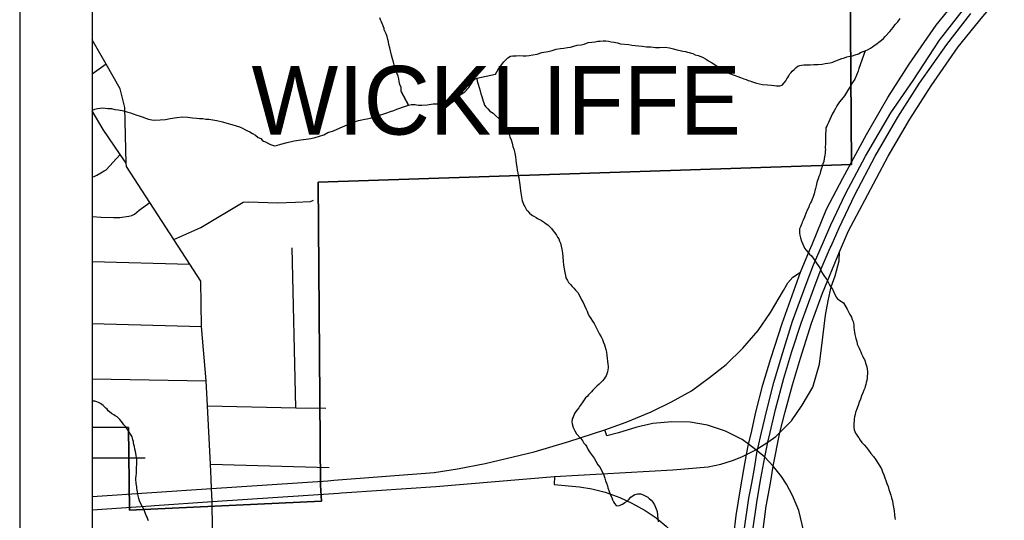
# Model space of a CAD drawing. Extents: x 0 to 44.3, y 0 to 22.
# Drawn here: x 2 to 3.359, y 14.762 to 15.453 of the extents above; entities that cross this region are included whole.
import ezdxf

# ---------------------------------------------------------------- set-up
doc = ezdxf.new("R2010")
doc.units = 0
for name, color, linetype in [('GM_X_City_Street', 7, 'Continuous'), ('GM_X_Corporation', 7, 'Continuous'), ('GM_X_Corporation_Text', 7, 'Continuous'), ('GM_X_County_Road', 7, 'Continuous'), ('GM_X_Interchange_Ramps', 7, 'Continuous'), ('GM_X_Interstate_Route', 7, 'Continuous'), ('GM_X_Interstate_Shield', 7, 'Continuous'), ('GM_X_Minor_River', 7, 'Continuous'), ('SH_Data', 7, 'Continuous')]:
    doc.layers.add(name, color=color, linetype=linetype)

msp = doc.modelspace()

# ---------------------------------------------------------------- linework, layer by layer
at = {"layer": 'GM_X_City_Street'}
for p, q in [((2.1193, 15.3916), (2.1, 15.3781)), ((2.3812, 14.9177), (2.3763, 15.1381)), ((2.1, 15.1194), (2.2347, 15.116)), ((2.1, 15.0339), (2.2508, 15.0296)), ((2.1, 14.9574), (2.2574, 14.9549)), ((2.2632, 14.8398), (2.4271, 14.8353))]:
    msp.add_line(p, q, dxfattribs=at)
for points in [[(2.1472, 15.255), (2.1388, 15.2673), (2.1152, 15.3018), (2.1, 15.3272)], [(2.1, 15.2361), (2.1028, 15.2367), (2.1065, 15.2385), (2.112, 15.2417), (2.1166, 15.2444), (2.1193, 15.2461), (2.1388, 15.2673)], [(2.1, 15.1815), (2.1126, 15.1807), (2.1297, 15.1804), (2.1384, 15.1804), (2.1507, 15.1818), (2.155, 15.183), (2.1586, 15.185), (2.1651, 15.1901), (2.1796, 15.2009)], [(2.2127, 15.1498), (2.2502, 15.1663), (2.3083, 15.2013), (2.3165, 15.202), (2.3555, 15.2005), (2.3807, 15.2012), (2.4012, 15.2024), (2.4057, 15.204)], [(2.2593, 14.9202), (2.3812, 14.9177), (2.4225, 14.9169)]]:
    msp.add_lwpolyline(points, dxfattribs=at)
at = {"layer": 'GM_X_Corporation'}
for points in [[(2.1, 18.9995), (2.1, 14.1), (8.9, 14.1), (8.9, 20.9)], [(2.1, 18.9995), (2.1, 14.1), (8.9, 14.1), (8.9, 20.9)], [(3.1444, 15.7503), (3.148, 15.2535), (2.4119, 15.2288), (2.4154, 14.8107), (2.4165, 14.7887), (2.1516, 14.7764), (2.1501, 14.8903), (2.1, 14.8909), (2.1, 14.1), (5.9487, 14.1)]]:
    msp.add_lwpolyline(points, dxfattribs=at)
msp.add_lwpolyline([(2.1, 17.1027), (2.1, 14.8909), (2.1501, 14.8903), (2.1516, 14.7764), (2.4165, 14.7887), (2.4154, 14.8107), (2.4119, 15.2288), (3.148, 15.2535), (3.1444, 15.7503), (3.1447, 15.8221), (3.0821, 15.82), (3.0702, 16.3994), (3.0704, 16.4866), (2.9251, 16.4817), (2.9204, 16.6966), (2.9192, 16.8391), (2.9156, 16.875), (2.9148, 16.9035), (2.8787, 16.9814), (2.7996, 16.9364), (2.538, 16.7829), (2.4871, 16.7475), (2.4335, 16.7048), (2.4288, 17.1065)], close=True, dxfattribs=at)
at = {"layer": 'GM_X_County_Road'}
for points in [[(2.2642, 14.8195), (2.2632, 14.8398), (2.2593, 14.9202), (2.2574, 14.9549), (2.2508, 15.0296), (2.25, 15.0923), (2.2347, 15.116), (2.2127, 15.1498), (2.1796, 15.2009), (2.1473, 15.2506), (2.1472, 15.255), (2.145, 15.332), (2.1386, 15.3579), (2.1193, 15.3916), (2.1, 15.4255)], [(2.2658, 14.7884), (2.2649, 14.8063), (2.2642, 14.8195)], [(2.4297, 14.1), (2.4207, 14.3258), (2.4124, 14.6523), (2.4009, 14.6634), (2.2662, 14.7501), (2.2658, 14.7884)]]:
    msp.add_lwpolyline(points, dxfattribs=at)
at = {"layer": 'GM_X_Interchange_Ramps'}
for points in [[(3.0823, 14.747), (3.0756, 14.7757), (3.0666, 14.7966), (3.0585, 14.812), (3.0516, 14.8226), (3.0426, 14.8342), (3.0399, 14.8369), (3.0285, 14.8496), (3.0182, 14.8582), (3.0163, 14.8598), (3.0061, 14.8674), (2.9973, 14.8738), (2.9741, 14.8855), (2.9493, 14.8937), (2.9257, 14.8978), (2.9002, 14.8981), (2.8738, 14.8958), (2.8518, 14.8909), (2.8266, 14.8831), (2.8107, 14.8789), (2.8077, 14.8871)], [(2.7382, 14.8228), (2.738, 14.8117), (2.7727, 14.8086), (2.7897, 14.8059), (2.8081, 14.801), (2.8285, 14.7936), (2.8449, 14.7862), (2.8634, 14.7759), (2.8786, 14.7656), (2.8926, 14.7541), (2.9056, 14.7418), (2.9176, 14.728), (2.9277, 14.7148), (2.9351, 14.7035), (2.9429, 14.6885), (2.9483, 14.6767), (2.9535, 14.6634), (2.9574, 14.6514), (2.9606, 14.6413), (2.9643, 14.6217), (2.9663, 14.6055), (2.9675, 14.5884), (2.9749, 14.5885)]]:
    msp.add_lwpolyline(points, dxfattribs=at)
at = {"layer": 'GM_X_Interstate_Route'}
msp.add_line((2.1, 14.7769), (2.1812, 14.7825), dxfattribs=at)
for points in [[(3.0938, 15.1431), (3.1139, 15.1918), (3.1362, 15.2345), (3.1687, 15.2948), (3.1985, 15.3459), (3.2277, 15.392), (3.2652, 15.4457), (3.299, 15.4878), (3.3373, 15.5321), (3.3832, 15.5819), (3.4083, 15.6088), (3.4177, 15.6193), (3.5644, 15.7458), (3.6806, 15.8429), (3.73, 15.8849), (3.7765, 15.9233), (3.8936, 16.0217)], [(3.1316, 15.1329), (3.1442, 15.1616), (3.1665, 15.2043), (3.199, 15.2646), (3.2288, 15.3157), (3.258, 15.3618), (3.2955, 15.4155), (3.3293, 15.4576), (3.3514, 15.4831)], [(2.9999, 14.7482), (3.0063, 14.7927), (3.0108, 14.8135), (3.0146, 14.8368), (3.0182, 14.8582), (3.0187, 14.8613), (3.0242, 14.8835), (3.0312, 14.9141), (3.0409, 14.9524), (3.0515, 14.9881), (3.0669, 15.0372), (3.0857, 15.088), (3.0958, 15.115), (3.1096, 15.1464), (3.1199, 15.17), (3.1401, 15.2129), (3.1675, 15.265), (3.2026, 15.3246), (3.2331, 15.3691), (3.2699, 15.4248), (3.3028, 15.4674)], [(3.0117, 14.7456), (3.0179, 14.7902), (3.0229, 14.8199), (3.0285, 14.8496), (3.0329, 14.8703), (3.0361, 14.8837), (3.0434, 14.9152), (3.0549, 14.9584), (3.066, 14.9951), (3.0787, 15.0342), (3.0961, 15.0824), (3.1062, 15.1093), (3.1189, 15.1381), (3.12, 15.1405), (3.131, 15.1657), (3.1527, 15.2116), (3.181, 15.2648), (3.212, 15.3185), (3.2421, 15.3654), (3.2796, 15.4189), (3.3129, 15.4619)], [(2.4255, 14.817), (2.4335, 14.8175), (2.5723, 14.8285), (2.6045, 14.8332), (2.6427, 14.8408), (2.7102, 14.8568), (2.7579, 14.871), (2.8077, 14.8871), (2.8372, 14.8977), (2.8717, 14.9118), (2.8998, 14.9256), (2.9273, 14.9411), (2.9522, 14.9592), (2.975, 14.9773), (2.9981, 14.9999), (3.0194, 15.0241), (3.0365, 15.049), (3.0545, 15.0796), (3.0601, 15.0901), (3.0672, 15.098), (3.0779, 15.1049), (3.0903, 15.1346), (3.0938, 15.1431)], [(2.9967, 14.8501), (3.0004, 14.8516), (3.0034, 14.8531), (3.0163, 14.8598), (3.0187, 14.8613), (3.0329, 14.8703), (3.0437, 14.8778), (3.0495, 14.8837), (3.0653, 14.8994), (3.0802, 14.9214), (3.0947, 14.9461), (3.1041, 14.978), (3.1085, 15.0149), (3.1123, 15.0453), (3.1158, 15.0652), (3.1202, 15.0847), (3.1255, 15.0995), (3.131, 15.1206), (3.1316, 15.1329)], [(3.0495, 14.8837), (3.0568, 14.9119), (3.0667, 14.9494), (3.0778, 14.9861), (3.0932, 15.0343), (3.1083, 15.0758), (3.1316, 15.1329)], [(2.9986, 14.1), (2.9816, 14.3787), (2.9796, 14.4203), (2.9748, 14.5117), (2.9742, 14.5499), (2.9749, 14.5885), (2.9766, 14.6288), (2.9784, 14.6635), (2.9821, 14.7081), (2.9857, 14.7414), (2.9892, 14.7689), (2.9955, 14.8083), (2.9994, 14.8323), (3.0034, 14.8531), (3.0061, 14.8674), (3.0095, 14.8818), (3.016, 14.9117), (3.0259, 14.9492), (3.037, 14.9858), (3.0524, 15.0341), (3.0779, 15.1049)], [(3.0149, 14.5118), (3.0142, 14.55), (3.014, 14.5886), (3.0155, 14.6266), (3.0175, 14.664), (3.0215, 14.7102), (3.0256, 14.7459), (3.0305, 14.7819), (3.0362, 14.8137), (3.0399, 14.8369), (3.0495, 14.8837)], [(2.7382, 14.8228), (2.9017, 14.8322), (2.9504, 14.8361), (2.9677, 14.84), (2.9839, 14.8449), (2.9967, 14.8501)], [(2.1, 14.795), (2.2649, 14.8063), (2.4255, 14.817)], [(2.4444, 14.8003), (2.4516, 14.8008), (2.5743, 14.8092), (2.7382, 14.8228)], [(2.1812, 14.7825), (2.1862, 14.7829), (2.2658, 14.7884), (2.4403, 14.8), (2.4444, 14.8003)]]:
    msp.add_lwpolyline(points, dxfattribs=at)
at = {"layer": 'GM_X_Interstate_Shield'}
msp.add_line((2.1, 14.8486), (2.1733, 14.8486), dxfattribs=at)
at = {"layer": 'GM_X_Minor_River'}
for points in [[(2.5265, 15.3541), (2.5367, 15.3353), (2.5265, 15.3541), (2.5264, 15.3594), (2.5248, 15.3635), (2.524, 15.3677), (2.5232, 15.3715), (2.5223, 15.3753), (2.5211, 15.3786), (2.5199, 15.3828), (2.5183, 15.387), (2.5171, 15.3907), (2.5159, 15.3945), (2.5147, 15.399), (2.5134, 15.404), (2.5118, 15.41), (2.511, 15.4145), (2.5097, 15.4187), (2.5089, 15.4225), (2.5081, 15.4259), (2.5073, 15.43), (2.5057, 15.4338), (2.5045, 15.4365), (2.5033, 15.4391), (2.5029, 15.441), (2.4993, 15.45), (2.4981, 15.4531), (2.4969, 15.4557)], [(3.072, 15.3873), (3.0739, 15.3888), (3.0769, 15.39), (3.0791, 15.3904), (3.0826, 15.3909), (3.0867, 15.391), (3.0913, 15.391), (3.0962, 15.3911), (3.1019, 15.3912), (3.1076, 15.3917), (3.1117, 15.3926), (3.1155, 15.393), (3.1186, 15.3938), (3.1223, 15.3946), (3.125, 15.3958), (3.128, 15.397), (3.1314, 15.3982), (3.1348, 15.3994), (3.1385, 15.4006), (3.1419, 15.4018), (3.1457, 15.4027), (3.1495, 15.4035), (3.1533, 15.4047), (3.1578, 15.4059), (3.1615, 15.4083), (3.1672, 15.4103), (3.171, 15.4119), (3.1743, 15.4138), (3.1773, 15.4158), (3.1796, 15.4173), (3.1818, 15.4189), (3.1837, 15.4205), (3.1859, 15.422), (3.1878, 15.4236), (3.1897, 15.4251), (3.1923, 15.4271), (3.1949, 15.4298), (3.2012, 15.4367), (3.2035, 15.4394), (3.2057, 15.4425), (3.2086, 15.4464), (3.212, 15.4502), (3.2153, 15.4548)], [(2.6309, 15.3723), (2.6566, 15.3781), (2.6603, 15.3846), (2.6651, 15.3908), (2.6684, 15.395), (2.6714, 15.3981), (2.674, 15.4005), (2.6774, 15.4028), (2.6808, 15.4032), (2.6854, 15.4033), (2.6903, 15.4038), (2.6948, 15.4035), (2.699, 15.4032), (2.7032, 15.4037), (2.7081, 15.4045), (2.7142, 15.4058), (2.7206, 15.4078), (2.7293, 15.4094), (2.7349, 15.4107), (2.7406, 15.4123), (2.7463, 15.4132), (2.7512, 15.414), (2.7561, 15.4149), (2.7603, 15.4153), (2.7648, 15.4166), (2.7697, 15.4178), (2.775, 15.4186), (2.7792, 15.4195), (2.7848, 15.4215), (2.7897, 15.4223), (2.7943, 15.4228), (2.7981, 15.4236), (2.8015, 15.4237), (2.8053, 15.4241), (2.8091, 15.4238), (2.8129, 15.4235), (2.8163, 15.4228), (2.8205, 15.4221), (2.8251, 15.4211), (2.8293, 15.42), (2.8407, 15.4187), (2.8452, 15.418), (2.8498, 15.4177), (2.8544, 15.4171), (2.8593, 15.4164), (2.865, 15.4157), (2.8711, 15.4155), (2.8776, 15.4148), (2.8832, 15.4149), (2.8908, 15.4151), (2.8969, 15.4144), (2.9023, 15.413), (2.9072, 15.4116), (2.9118, 15.4105), (2.9156, 15.4098), (2.919, 15.4091), (2.9217, 15.4084), (2.924, 15.4077), (2.9267, 15.407), (2.9293, 15.4063), (2.9324, 15.4048), (2.9366, 15.4038), (2.9404, 15.4023), (2.9435, 15.4009), (2.9469, 15.399), (2.9508, 15.3964), (2.955, 15.3939), (2.96, 15.3909), (2.9646, 15.3876), (2.9696, 15.3842), (2.9746, 15.3813), (2.9799, 15.3791), (2.9864, 15.3766), (2.9914, 15.3748), (2.9952, 15.3733), (2.9994, 15.3715), (3.0029, 15.3704), (3.0055, 15.3693), (3.0078, 15.3686), (3.0101, 15.3679), (3.0128, 15.3668), (3.017, 15.3657), (3.0212, 15.3647), (3.0254, 15.3636), (3.0322, 15.3634), (3.0375, 15.3627), (3.0413, 15.3624), (3.0448, 15.3621), (3.0474, 15.3617), (3.0493, 15.3618), (3.0527, 15.363), (3.0553, 15.3661), (3.0575, 15.3688), (3.059, 15.3715), (3.0605, 15.3734), (3.0616, 15.3757), (3.0631, 15.3784), (3.0649, 15.3803), (3.0664, 15.3822), (3.069, 15.3846), (3.072, 15.3873)], [(3.1672, 15.4103), (3.1582, 15.3858), (3.1575, 15.382), (3.1553, 15.3766), (3.1528, 15.3713), (3.1498, 15.3663), (3.1469, 15.3613), (3.1439, 15.3571), (3.1413, 15.3528), (3.1384, 15.3482), (3.1343, 15.3428), (3.1317, 15.3397), (3.1299, 15.3371), (3.128, 15.3344), (3.1262, 15.3305), (3.1244, 15.3275), (3.1229, 15.3251), (3.1214, 15.3228), (3.12, 15.3194), (3.1163, 15.3114), (3.1152, 15.3083), (3.1141, 15.3064), (3.113, 15.3037), (3.1127, 15.3014), (3.1128, 15.2988), (3.1124, 15.2965), (3.1121, 15.2938), (3.1121, 15.2908), (3.1122, 15.2881), (3.1123, 15.2847), (3.1123, 15.2828), (3.1123, 15.2809), (3.112, 15.2782), (3.112, 15.2759), (3.1121, 15.2741), (3.1117, 15.2718), (3.1118, 15.2691), (3.1115, 15.2664), (3.1108, 15.2638), (3.1104, 15.2615), (3.1101, 15.2573), (3.1087, 15.2542), (3.1076, 15.2504), (3.1065, 15.247), (3.1054, 15.2435), (3.1044, 15.2397), (3.1029, 15.2367), (3.1022, 15.2336), (3.1011, 15.2313), (3.1004, 15.2286), (3.0997, 15.2263), (3.0994, 15.2241), (3.0983, 15.2202), (3.0976, 15.2172), (3.0973, 15.2153), (3.0965, 15.213), (3.0958, 15.2099), (3.0947, 15.2073), (3.094, 15.2054), (3.0929, 15.2027), (3.0918, 15.2004), (3.09, 15.1969), (3.0893, 15.1946), (3.0875, 15.1912), (3.0864, 15.1889), (3.0856, 15.187), (3.0831, 15.1808), (3.0817, 15.1766), (3.0802, 15.1736), (3.0795, 15.1717), (3.0777, 15.1671), (3.0766, 15.1644), (3.0762, 15.1625), (3.0763, 15.1587), (3.0771, 15.156), (3.0779, 15.1523), (3.0792, 15.1477), (3.0808, 15.1436), (3.0824, 15.1402), (3.0835, 15.1379), (3.0855, 15.1353), (3.0882, 15.1319), (3.0901, 15.1297), (3.0928, 15.1271), (3.0952, 15.1241), (3.0975, 15.1207), (3.0999, 15.1173), (3.1022, 15.114), (3.1045, 15.1106), (3.1069, 15.1053), (3.1089, 15.1016), (3.1108, 15.0989), (3.1124, 15.0967), (3.114, 15.0944), (3.1155, 15.0918), (3.1175, 15.0884), (3.1194, 15.085), (3.1218, 15.0813), (3.1238, 15.0771), (3.1253, 15.0737), (3.1273, 15.07)], [(2.5458, 15.3362), (2.5477, 15.3358), (2.5504, 15.3351), (2.5553, 15.3352), (2.5625, 15.3357), (2.5709, 15.337), (2.5777, 15.3372), (2.583, 15.3372), (2.5875, 15.3377), (2.591, 15.3382), (2.5944, 15.339), (2.597, 15.3394), (2.5989, 15.3402), (2.6008, 15.3414), (2.6026, 15.3425), (2.6056, 15.3464), (2.6093, 15.3506), (2.6146, 15.3538), (2.6168, 15.3557), (2.6183, 15.3576), (2.6202, 15.3596), (2.6212, 15.3619), (2.6235, 15.3653), (2.6257, 15.3684), (2.6283, 15.3711), (2.6309, 15.3723), (2.6314, 15.3685), (2.633, 15.3644), (2.6342, 15.3595), (2.6354, 15.3549), (2.6366, 15.3508), (2.6378, 15.347), (2.639, 15.344), (2.6399, 15.3406), (2.6407, 15.3383), (2.6415, 15.3353), (2.6434, 15.3327), (2.6461, 15.3301), (2.6492, 15.3271), (2.6535, 15.3241), (2.6573, 15.3204), (2.6612, 15.317), (2.6651, 15.3126), (2.667, 15.3088), (2.6694, 15.3054), (2.6717, 15.302), (2.6741, 15.2987), (2.6756, 15.2953), (2.6768, 15.2915), (2.6784, 15.2874), (2.6797, 15.2828), (2.6809, 15.2783), (2.6821, 15.2745), (2.6833, 15.2688), (2.6842, 15.2639), (2.685, 15.2594), (2.6855, 15.2548), (2.6864, 15.2499), (2.6868, 15.2453), (2.6877, 15.2416), (2.6881, 15.2382), (2.6889, 15.2351), (2.6894, 15.2317), (2.6898, 15.2287), (2.6902, 15.2253), (2.6907, 15.2211), (2.6911, 15.2173), (2.6916, 15.2143), (2.6937, 15.2033), (2.6949, 15.1999), (2.6961, 15.1973), (2.6973, 15.1954), (2.6988, 15.1928), (2.6996, 15.1909), (2.7012, 15.189), (2.7039, 15.186), (2.7058, 15.1845), (2.7077, 15.1831), (2.7097, 15.182), (2.7127, 15.1801), (2.7146, 15.179), (2.7166, 15.1779), (2.7189, 15.1768), (2.7219, 15.175), (2.7246, 15.1731), (2.7269, 15.1716), (2.7292, 15.1702), (2.7315, 15.1679), (2.7339, 15.1649), (2.7366, 15.1619), (2.7385, 15.1589), (2.7409, 15.1556), (2.7425, 15.1529), (2.744, 15.1507), (2.7452, 15.1477), (2.7464, 15.1446), (2.7476, 15.1405), (2.7485, 15.1363), (2.7493, 15.131), (2.7498, 15.1257), (2.7503, 15.1197)], [(2.1, 15.3283), (2.1004, 15.3283), (2.1038, 15.3296), (2.1076, 15.3304), (2.111, 15.3312), (2.1148, 15.3313), (2.1178, 15.3309), (2.1216, 15.3306), (2.1266, 15.3304), (2.1312, 15.3293), (2.1361, 15.3286), (2.1414, 15.328), (2.1452, 15.3269), (2.1491, 15.3254), (2.1529, 15.3244), (2.1567, 15.3233), (2.1617, 15.3215), (2.1651, 15.3204), (2.1678, 15.3197), (2.1705, 15.3186), (2.1735, 15.3172), (2.1777, 15.3161), (2.1823, 15.315), (2.1865, 15.3144), (2.2013, 15.3154), (2.2077, 15.317), (2.2171, 15.318), (2.2247, 15.3189), (2.2319, 15.3186), (2.2384, 15.3176), (2.2441, 15.3173), (2.2483, 15.317), (2.2528, 15.3167), (2.257, 15.316), (2.2612, 15.3157), (2.2665, 15.3151), (2.2719, 15.314), (2.2799, 15.3123), (2.286, 15.3105), (2.2928, 15.3087), (2.2986, 15.3069), (2.3035, 15.3051), (2.3074, 15.3033), (2.3108, 15.3018), (2.3143, 15.3), (2.3177, 15.2982), (2.3215, 15.2963), (2.3254, 15.2938), (2.3292, 15.2908), (2.3327, 15.289), (2.3346, 15.2871), (2.3365, 15.2856), (2.3392, 15.2845), (2.3434, 15.2823), (2.3461, 15.2808), (2.3488, 15.2798), (2.3518, 15.2791), (2.3545, 15.2795), (2.3605, 15.2815), (2.3692, 15.2839), (2.379, 15.286), (2.3881, 15.2873), (2.3953, 15.2882), (2.4021, 15.2891), (2.4078, 15.2907), (2.4138, 15.2923), (2.4199, 15.2944), (2.4255, 15.2975), (2.433, 15.2999), (2.4383, 15.3023), (2.456, 15.3098), (2.462, 15.3122), (2.4677, 15.3142), (2.4722, 15.3151), (2.4764, 15.3159), (2.4798, 15.3164), (2.4836, 15.3172), (2.4885, 15.3188), (2.4922, 15.32), (2.4968, 15.3212), (2.5013, 15.3228), (2.5066, 15.3248), (2.5119, 15.3264), (2.5164, 15.328), (2.5205, 15.3296), (2.5247, 15.3309), (2.5284, 15.3324), (2.5326, 15.334), (2.5367, 15.3353), (2.5409, 15.3361), (2.5428, 15.3361), (2.5458, 15.3362)], [(2.7503, 15.1197), (2.7508, 15.1143), (2.7516, 15.1094), (2.7525, 15.1045), (2.7533, 15.1003), (2.7541, 15.0969), (2.7561, 15.0932), (2.7577, 15.0905), (2.7604, 15.0876), (2.7627, 15.0849), (2.765, 15.0827), (2.7674, 15.0801), (2.7693, 15.0778), (2.7709, 15.076), (2.7756, 15.0666), (2.7779, 15.0628), (2.7795, 15.0587), (2.7815, 15.0545), (2.7831, 15.0507), (2.7847, 15.047), (2.7866, 15.0436), (2.7886, 15.0406), (2.7906, 15.0372), (2.7929, 15.0338), (2.7953, 15.0293), (2.7976, 15.0248), (2.8004, 15.0192), (2.8027, 15.0154), (2.8047, 15.0116), (2.8059, 15.0079), (2.8071, 15.0045), (2.8083, 15.0011), (2.8091, 14.998), (2.81, 14.9943), (2.8104, 14.9897), (2.8109, 14.9855), (2.8113, 14.9818), (2.8118, 14.9776), (2.8122, 14.9749), (2.8123, 14.9727), (2.8119, 14.97), (2.8112, 14.9673), (2.8105, 14.9643), (2.8094, 14.9616), (2.8083, 14.9597), (2.8069, 14.9574), (2.8046, 14.9547), (2.8024, 14.9523), (2.7998, 14.95), (2.7968, 14.9473), (2.7949, 14.9457), (2.7931, 14.9438), (2.7912, 14.9419), (2.7894, 14.9396), (2.7871, 14.9372), (2.7853, 14.9353), (2.7834, 14.9334), (2.7812, 14.9314), (2.7793, 14.9287), (2.7775, 14.9257), (2.7741, 14.9214), (2.7727, 14.9195), (2.7716, 14.9176), (2.7693, 14.9149), (2.7679, 14.9126), (2.766, 14.9095), (2.7642, 14.9045), (2.7627, 14.9022), (2.7621, 14.898), (2.7625, 14.8954), (2.7641, 14.8905), (2.7661, 14.886), (2.7684, 14.8818), (2.7746, 14.8751), (2.7774, 14.8714), (2.7789, 14.8687), (2.7809, 14.8665), (2.7828, 14.8635), (2.7848, 14.8597), (2.7875, 14.8556), (2.7903, 14.8518), (2.793, 14.8481), (2.7953, 14.844), (2.7981, 14.8391), (2.8012, 14.8353), (2.8028, 14.8319), (2.8044, 14.8286), (2.8063, 14.8244), (2.8075, 14.8206), (2.8088, 14.8169), (2.81, 14.8135), (2.8112, 14.8101), (2.812, 14.807), (2.8132, 14.8036), (2.814, 14.8006), (2.8156, 14.7968), (2.8172, 14.7938), (2.8184, 14.7904), (2.8199, 14.7878), (2.8211, 14.7856), (2.8234, 14.7829)], [(3.1273, 15.07), (3.1289, 15.0681), (3.1316, 15.0659), (3.135, 15.064), (3.1373, 15.0622), (3.142, 15.0539), (3.1436, 15.0509), (3.1452, 15.0483), (3.1468, 15.0449), (3.1483, 15.0426), (3.1491, 15.0396), (3.1503, 15.0366), (3.1511, 15.0343), (3.1516, 15.0317), (3.1516, 15.0286), (3.1521, 15.0245), (3.1525, 15.0218), (3.1529, 15.0188), (3.1534, 15.0169), (3.1542, 15.0131), (3.1554, 15.009), (3.1562, 15.0056), (3.1574, 15.0025), (3.1586, 14.9999), (3.1598, 14.9977), (3.161, 14.995), (3.1622, 14.992), (3.1638, 14.9882), (3.165, 14.986), (3.1661, 14.9841), (3.1669, 14.9814), (3.1677, 14.9792), (3.1685, 14.9769), (3.1693, 14.9743), (3.1698, 14.9709), (3.1702, 14.9678), (3.1703, 14.9644), (3.17, 14.9614), (3.17, 14.9583), (3.1693, 14.9553), (3.1686, 14.9526), (3.1679, 14.9496), (3.1672, 14.9469), (3.1665, 14.9446), (3.1654, 14.9419), (3.164, 14.9381), (3.1621, 14.9339), (3.1607, 14.9297), (3.1589, 14.9255), (3.1575, 14.9209), (3.1553, 14.9148), (3.1538, 14.9113), (3.1531, 14.9083), (3.1524, 14.9052), (3.1517, 14.9025), (3.1515, 14.8938), (3.1516, 14.8904), (3.152, 14.8874), (3.1528, 14.8851), (3.1536, 14.8824), (3.1552, 14.8806), (3.1564, 14.8783), (3.1583, 14.8761), (3.1603, 14.8731), (3.1626, 14.8697), (3.1657, 14.8663), (3.1688, 14.863), (3.1719, 14.8589), (3.175, 14.8547), (3.1785, 14.8502), (3.1816, 14.8457), (3.1851, 14.8409), (3.1875, 14.8371), (3.1895, 14.8333), (3.1911, 14.8292), (3.193, 14.8251), (3.1943, 14.8209), (3.1958, 14.8171), (3.1971, 14.813), (3.1986, 14.8092), (3.1999, 14.8047), (3.2011, 14.8013), (3.2023, 14.7971), (3.2035, 14.7933), (3.2047, 14.7892), (3.2052, 14.785), (3.206, 14.7805), (3.2069, 14.7756), (3.2074, 14.7699), (3.2082, 14.7657), (3.2086, 14.7638), (3.2086, 14.7634)], [(2.1636, 14.7959), (2.1632, 14.7989), (2.1627, 14.8015), (2.1623, 14.8038), (2.1619, 14.8061), (2.1615, 14.8084), (2.1614, 14.8106), (2.161, 14.8129), (2.1606, 14.8148), (2.1605, 14.8178), (2.1605, 14.8205), (2.1608, 14.8239), (2.1611, 14.8273), (2.1614, 14.8308), (2.1614, 14.8334), (2.1613, 14.8361), (2.1617, 14.8391), (2.1616, 14.8418), (2.1616, 14.8441), (2.1615, 14.8463), (2.1611, 14.849), (2.1607, 14.8516), (2.1602, 14.8551), (2.1598, 14.8573), (2.159, 14.8603), (2.1585, 14.8641), (2.1577, 14.8668), (2.1573, 14.8691), (2.1569, 14.8713), (2.1561, 14.8736), (2.1557, 14.8755), (2.1552, 14.8774), (2.1537, 14.88), (2.1521, 14.8826), (2.1509, 14.8845), (2.1494, 14.8864), (2.1478, 14.889), (2.1459, 14.8916), (2.1439, 14.8943), (2.142, 14.8969), (2.14, 14.8991), (2.1381, 14.9014), (2.1365, 14.9032), (2.1346, 14.9051), (2.1319, 14.9066), (2.13, 14.9081), (2.1269, 14.9099), (2.1239, 14.9121), (2.1219, 14.9136), (2.1208, 14.9155), (2.1188, 14.9173), (2.1169, 14.9188), (2.1153, 14.9207), (2.1134, 14.9222), (2.1115, 14.9237), (2.1088, 14.9248), (2.1065, 14.9258), (2.1035, 14.9266), (2.1008, 14.9269), (2.1, 14.927)], [(2.1779, 14.7616), (2.1767, 14.7638), (2.1759, 14.7665), (2.1747, 14.7691), (2.1732, 14.7725), (2.1716, 14.7766), (2.1668, 14.786), (2.1653, 14.7894), (2.1644, 14.7925), (2.1636, 14.7959)], [(2.8234, 14.7829), (2.8265, 14.7822), (2.8288, 14.783), (2.8321, 14.7846), (2.8351, 14.787), (2.8385, 14.7889), (2.8404, 14.7905), (2.8437, 14.7943), (2.8467, 14.7967), (2.8493, 14.7978), (2.8527, 14.7987), (2.8573, 14.7988), (2.8596, 14.798), (2.8669, 14.7944), (2.8688, 14.7925), (2.8715, 14.7899), (2.8742, 14.7873), (2.8762, 14.7839), (2.8782, 14.779), (2.8798, 14.7745), (2.8806, 14.7692), (2.8811, 14.7642), (2.8812, 14.7601)]]:
    msp.add_lwpolyline(points, dxfattribs=at)
at = {"layer": 'SH_Data'}
for p, q in [((2, 21), (2, 14)), ((2.1, 20.9), (2.1, 14.1)), ((2.1, 20.9), (2.1, 14.1))]:
    msp.add_line(p, q, dxfattribs=at)

# ---------------------------------------------------------------- texts
at = {"layer": 'GM_X_Corporation_Text'}
msp.add_text('WICKLIFFE', height=0.0947, rotation=0, dxfattribs=at).set_placement((2.3201, 15.2946))

doc.saveas('drawing.dxf')
